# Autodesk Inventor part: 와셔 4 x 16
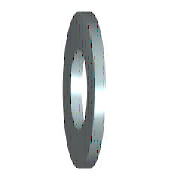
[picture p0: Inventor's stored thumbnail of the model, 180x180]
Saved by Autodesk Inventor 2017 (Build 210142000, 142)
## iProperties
IsCustomPart: 1
Created: 2012-02
Part Number: 와셔 4 x 16
Material: 강철, 연강
Description: 미터법 평면 와셔
Document SubType Name: Modeling
Standard: ANSI B18.22M
Designer: mduedu
Standard Revision: 1999
Standards Organization: ANSI
Language: ko-KR
Size Designation: 4 W
Categories: <MemberInstance><Categories><Category DisplayName="조임쇠" InternalName="e4da775c-781d-43d5-af7c-5136215cf5a6" Mnemonic="FSTN"><Category DisplayName="와셔" InternalN
Density: 1 g/cm^3
Appearance: 파란색 - 벽 페인트 - 광택
Author: mduedu
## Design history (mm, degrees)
sketch "스케치"
  geometry: C1 r 8 at (0, 0); C2 r 2.35 at (0, 0); 1 further point
  constraints: 2 centre point, 2 coincident
  dimensions: "d0" = 4.7 diameter of C2 (= SD1); "d1" = 16 diameter of C1 (= SD2)
extrude "본체" new body sketch "스케치" distance "d2" = 2.3 (= SD); taper "d3" = 0 deg
workaxis "Work Axis1"
workplane "Work Plane1"
body "Solid1"
other parameters: "SD1" = 4.7 [user parameter; used in 1 equation term], "SD2" = 16 [user parameter; used in 1 equation term], "SD" = 2.3 [user parameter; used in 1 equation term], "d4" = 0, "d5" = 0, "d6" = 0, "d7" = 0, "NND" = 4 [user parameter]
